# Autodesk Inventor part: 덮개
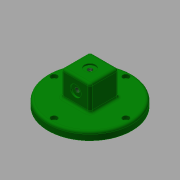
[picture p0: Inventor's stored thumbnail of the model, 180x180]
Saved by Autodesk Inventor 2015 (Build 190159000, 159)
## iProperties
Created: 2017-08
Part Number: 덮개
Material: 알루미늄 6061
Document SubType Name: Modeling
Designer: mduedu
Density: 1 g/cm^3
Appearance: 진녹색
Author: mduedu
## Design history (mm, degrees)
sketch "스케치1"
  geometry: C1 r 52.5 at (0, 0); 1 further point
  constraints: 1 centre point, 1 coincident
  dimensions: "d55" = 105 diameter of C1
extrude "돌출1" new body sketch "스케치1" distance "d5" = 10; taper "d6" = 0 deg
sketch "스케치2"
  geometry: L1 (-18, -18)-(18, -18); L2 (18, -18)-(18, 18); L3 (18, 18)-(-18, 18); L4 (-18, 18)-(-18, -18); L5 (-18, -18)-(18, 18); L6 (18, -18)-(-18, 18); 1 further point
  constraints: 12 end point, 2 midpoint, 2 parallel, 2 perpendicular, 1 horizontal
  dimensions: "d7" = 36 distance of L2.end L3.end
extrude "돌출2" join sketch "스케치2" distance "d9" = 32; taper "d10" = 0 deg
sketch "스케치3"
  geometry: C1 r 37 at (0, 0); 1 further point
  constraints: 1 centre point, 1 coincident
  dimensions: "d56" = 74 diameter of C1
extrude "돌출3" join sketch "스케치3" distance "d12" = 6; taper "d13" = 0 deg
sketch "스케치4"
  geometry: C1 r 33 at (0, 0); 1 further point
  constraints: 1 centre point, 1 coincident
  dimensions: "d57" = 66 diameter of C1
extrude "돌출4" cut sketch "스케치4" distance "d16" = 5; taper "d17" = 0 deg
sketch "스케치5"
  geometry: C1 r 9 at (0, 0); 1 further point
  constraints: 1 centre point, 1 coincident
  dimensions: "d18" = 18 diameter of C1
extrude "돌출5" cut sketch "스케치5" distance "d19" = 34; taper "d20" = 0 deg
sketch "스케치6"
  geometry: 2 further points
  constraints: 1 coincident
hole "구멍1" sketch "스케치6" at (0, 0) diameter "d21" = 5.917; stored, may be unused: countersink angle "d25" = 90 deg, drill point angle "d27" = 118 deg; dims "d22" = 6, "d23" = 14, "d24" = 2, "d26" = 8
sketch "스케치7"
  geometry: L1 (-34.5, -10)-(70.5, -10) reference; 3 further points
  constraints: 1 midpoint, 1 vertical alignment
  dimensions: "d58" = 26 distance from line of point (18, 16) L1
hole "구멍2" sketch "스케치7" at (18, 16) diameter "d29" = 5.917; stored, may be unused: countersink angle "d33" = 90 deg, drill point angle "d35" = 118 deg; dims "d30" = 6, "d31" = 14, "d32" = 2, "d34" = 8
fillet "모깎기2" dims "d37" = 3
fillet "모깎기3" dims "d38" = 3
fillet "모깎기4" dims "d39" = 3
fillet "모깎기5" dims "d40" = 3
chamfer "모따기1" distance "d41" = 1; stored, may be unused: second distance "d42" = 2, angle "d43" = 45 deg
fillet "모깎기7" dims "d45" = 3
fillet "모깎기8" dims "d46" = 3
sketch "스케치10" dims "d59" = 90
  geometry: 3 further points
  constraints: 2 vertical alignment, 1 coincident, 2 other
hole "구멍4" sketch "스케치10" at (0, 45) diameter "d60" = 4.5; stored, may be unused: countersink angle "d64" = 90 deg, drill point angle "d66" = 118 deg; dims "d61" = 6, "d62" = 8, "d63" = 4.6, "d65" = 8
node "솔리드1"
pattern_circular "원형 패턴1" dims angle "d68" = 360 deg
